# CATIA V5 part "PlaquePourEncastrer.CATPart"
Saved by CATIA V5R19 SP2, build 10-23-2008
Part number: PoulieDeCharge
Bounding box of the stored display mesh (mm): x -89 to 18, y -30 to 30, z -30 to 30
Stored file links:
  D:\SCHOOL\FRANCE\BANC_POUTRE_EN_MOUSSE\PlaquePourEncastrer.CATPart
  C:\Program Files\Dassault Systemes\B19\intel_a\reffiles\standard\MetricThickPitch.txt
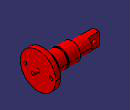
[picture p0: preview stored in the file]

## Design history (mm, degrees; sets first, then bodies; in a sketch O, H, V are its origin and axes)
AxisSystem1: origin (0, 0, 0), X (1, 0, 0), Y (0, 1, 0), Z (0, 0, 1)
Set1
  Plane1: type Offset, RefPlane YZ plane of AxisSystem1, Offset 20, reversed
  Plane2: type Offset, RefPlane end face of Pad3, Offset 16, reversed
Body1 (main body)
  Sketch1 on yz-plane, origin (0, 0, 0), H (0, 1, 0), V (0, 0, 1)
    circle A1 centre (0, 0) radius 30
    radius A1 = 30
  Pad1: profile Sketch1, direction (1, 0, 0), length 10
  Sketch2 on end face of Pad1, origin (10, 0, 0), H (0, 1, 0), V (0, 0, 1)
    circle A1 centre (0, 0) radius 3
    radius A1 = 3
  Pad2: profile Sketch2, direction (1, 0, 0), length 8
  Sketch3 on start face of Pad1, origin (0, 0, 0), H (0, -1, 0), V (0, 0, 1)
    circle A1 centre (0, 0) radius 17
    radius A1 = 17
  Pad3: profile Sketch3, direction (-1, 0, 0), length 9
  Sketch4 on end face of Pad3, origin (-9, 0, 0), H (0, -1, 0), V (0, 0, 1)
    circle A1 centre (0, 0) radius 12
    radius A1 = 12
  Pad4: profile Sketch4, direction (-1, 0, 0), length 80
  Chamfer1: length 2, angle 45, on edge [face of Pad4 from Sketch4.A1 | end face of Pad4]
  Sketch5 on end face of Pad1, origin (10, 0, 0), H (0, 1, 0), V (0, 0, 1)
    point P1 (22, 0)
    axis line L1 (-22.395, 0) -> (45.7979, 0)
    reference projected point E1 (0, 0) from vertex [YZ plane of AxisSystem1 | ZX plane of AxisSystem1 | XY plane of AxisSystem1]
    distance P1 E1 = 22
    coincidence: L1 O, P1 L1
    horizontal: L1 H
  Hole1: placed by Sketch5, at (10, 22, 0) direction (-1, 0, 0), diameter 6, through (limit type 3)
  RectPattern1: of Hole1, direction 1 instances 2, spacing 44, along edge [YZ plane of AxisSystem1 | XY plane of AxisSystem1] reversed
  Chamfer2: length 2, angle 45, on edge [start face of Pad1 | face of Pad1 from Sketch1.A1]
  Sketch6 on end face of Pad4, origin (-89, 0, 0), H (0, -1, 0), V (0, 0, 1)
    projected circle E1 centre (0, 0) radius 12 from edge [face of Pad4 from Sketch4.A1 | face of Chamfer1]
    projected arc E2 centre (0, 0) radius 12 from (5, -10.9087) to (5, 10.9087) ccw from edge [face of Pad4 from Sketch4.A1 | face of Chamfer1]
    projected arc E3 centre (0, 0) radius 12 from (-5, 10.9087) to (-5, -10.9087) ccw from edge [face of Pad4 from Sketch4.A1 | face of Chamfer1]
    line L1 (5, 10.9087) -> (5, -10.9087)
    line L2 (-5, 10.9087) -> (-5, -10.9087)
    point P1 (5, 10.9087)
    point P2 (-5, 10.9087)
    point P3 (-5, -10.9087)
    point P4 (5, -10.9087)
    distance L2 L1 = 10
    vertical: L1 V, L2 V
    symmetry: L1 L2 V
    coincidence: E1 P1, E1 P2, E1 P3, E1 P4
  Pocket1: profile Sketch6, direction (1, 0, 0), length 20
  Sketch7 on face of Pocket1 from Sketch6.L1, origin (-39.8479, -5, -0.5245), H (1, 0, 0), V (0, 0, 1)
    point P1 (-39.1521, 0.5245)
    reference projected line E1 through (0, 0.5245) direction (-1, 0) from axis of face of Pad4 from Sketch4.A1
    reference projected line E2 (-49.1521, 6.7695) -> (-49.1521, -5.7205) from edge [end face of Pad4 | face of Pocket1 from Sketch6.L1]
    distance E2 P1 = 10
    coincidence: P1 E1
  Hole2: placed by Sketch7, at (-79, -5, 0) direction (0, 1, 0), diameter 6, through (limit type 3)
  Sketch8 on end face of Pad3, origin (-9, 0, 0), H (0, -1, 0), V (0, 0, 1)
    circle A1 centre (0, 0) radius 15
    radius A1 = 15
  Pad5: profile Sketch8, direction (-1, 0, 0), length 38
  Sketch9 on Plane2, origin (-25, 0, 0), H (0, 1, 0), V (0, 0, 1)
    circle A1 centre (0, 0) radius 13.5
    radius A1 = 13.5
  Pocket2: profile Sketch9, direction (-1, 0, 0), length 2.6, outer side
  Sketch10 on end face of Pad4, origin (-89, 0, 0), H (0, -1, 0), V (0, 0, 1)
    line L1 (-3, 11.619) -> (-3, 7.619)
    line L2 (-3, 7.619) -> (3, 7.619)
    line L3 (3, 7.619) -> (3, 11.619)
    axis line L4 (0, 19.9309) -> (0, -11.8562)
    point P3 (0, 19.9309)
    projected circle E1 centre (0, 0) radius 12 from edge [face of Pad4 from Sketch4.A1 | face of Chamfer1]
    projected arc E2 centre (0, 0) radius 12 from (3, 11.619) to (-3, 11.619) ccw from edge [face of Pad4 from Sketch4.A1 | face of Chamfer1]
    point P5 (3, 11.619)
    point P6 (-3, 11.619)
    length L3 = 4
    length L2 = 6
    vertical: L1 V, L3 V, L4 V
    horizontal: L2 H
    coincidence: P3 V, E1 P5, E1 P6
    symmetry: L3 L1 L4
